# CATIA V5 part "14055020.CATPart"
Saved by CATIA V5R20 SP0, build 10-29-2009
Part number: 14055020
Definition: NONE
Nomenclature: 14055020
Source: Unknown
Description: 14055020
Bounding box of the stored display mesh (mm): x -10 to 40, y -41.5 to 31.6, z -31.6 to 31.6
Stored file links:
  C:\Users\Utente\Desktop\IO LAVORO\3D X SITO CF\X SITO\PLASTICA\RF2\14055020.CATPart
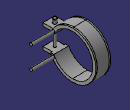
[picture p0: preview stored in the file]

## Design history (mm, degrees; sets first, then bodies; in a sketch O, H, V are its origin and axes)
Body1 "14055020" (main body)
  Solid1: solid without history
